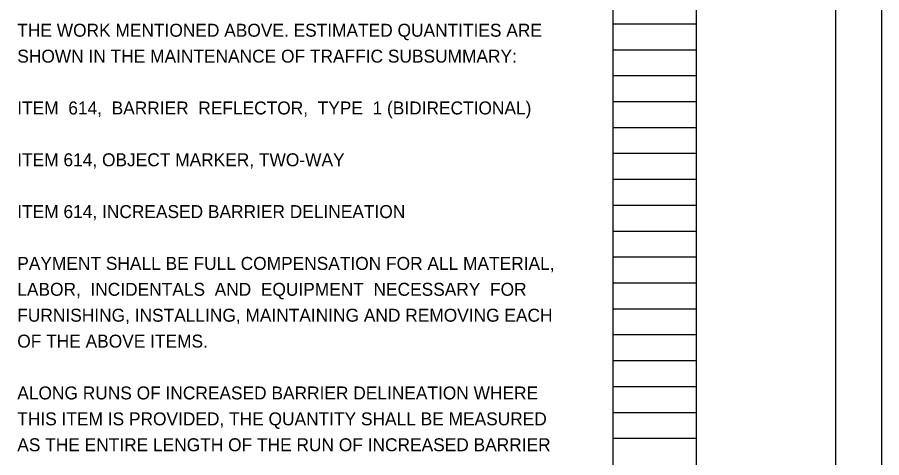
# Model space of a CAD drawing. Extents: x 0 to 34, y 0 to 22.
# Drawn here: x 24.66 to 34, y 4.69 to 9.45 of the extents above; entities that cross this region are included whole.
import ezdxf

# ---------------------------------------------------------------- set-up
doc = ezdxf.new("R2010")
doc.units = 0
for name, color, linetype in [('SH_Border', 7, 'Continuous'), ('SH_Cut_Line', 7, 'Continuous'), ('SH_Data', 7, 'Continuous'), ('SH_Text', 7, 'Continuous')]:
    doc.layers.add(name, color=color, linetype=linetype)

msp = doc.modelspace()

# ---------------------------------------------------------------- linework, layer by layer
at = {"layer": 'SH_Border'}
msp.add_line((32, 0.5), (32, 21.5), dxfattribs=at)
msp.add_lwpolyline([(1.5, 21.5), (33.5, 21.5), (33.5, 0.5), (1.5, 0.5)], close=True, dxfattribs=at)
at = {"layer": 'SH_Cut_Line'}
msp.add_lwpolyline([(0, 0), (34, 0), (34, 22), (0, 22)], close=True, dxfattribs=at)
at = {"layer": 'SH_Data'}
for p, q in [((31.1, 0.98), (31.1, 21.14)), ((32, 0.98), (32, 21.14)), ((31.1, 9.38), (32, 9.38)), ((31.1, 9.1), (32, 9.1)), ((31.1, 8.82), (32, 8.82)), ((31.1, 8.54), (32, 8.54)), ((31.1, 8.26), (32, 8.26)), ((31.1, 7.98), (32, 7.98)), ((31.1, 7.7), (32, 7.7)), ((31.1, 7.42), (32, 7.42)), ((31.1, 7.14), (32, 7.14)), ((31.1, 6.86), (32, 6.86)), ((31.1, 6.58), (32, 6.58)), ((31.1, 6.3), (32, 6.3)), ((31.1, 6.02), (32, 6.02)), ((31.1, 5.74), (32, 5.74)), ((31.1, 5.46), (32, 5.46)), ((31.1, 5.18), (32, 5.18)), ((31.1, 4.9), (32, 4.9))]:
    msp.add_line(p, q, dxfattribs=at)

# ---------------------------------------------------------------- texts
at = {"layer": 'SH_Text'}
for s, p in [('THE WORK MENTIONED ABOVE. ESTIMATED QUANTITIES ARE ', (24.66, 9.24)), ('SHOWN IN THE MAINTENANCE OF TRAFFIC SUBSUMMARY:', (24.66, 8.96)), ('ITEM  614,  BARRIER  REFLECTOR,  TYPE  1 (BIDIRECTIONAL) ', (24.66, 8.4)), ('ITEM 614, OBJECT MARKER, TWO-WAY ', (24.66, 7.84)), ('ITEM 614, INCREASED BARRIER DELINEATION ', (24.66, 7.28)), ('PAYMENT SHALL BE FULL COMPENSATION FOR ALL MATERIAL,', (24.66, 6.72)), ('LABOR,  INCIDENTALS  AND  EQUIPMENT  NECESSARY  FOR', (24.66, 6.44)), ('FURNISHING, INSTALLING, MAINTAINING AND REMOVING EACH', (24.66, 6.16)), ('OF THE ABOVE ITEMS.', (24.66, 5.88)), ('ALONG RUNS OF INCREASED BARRIER DELINEATION WHERE', (24.66, 5.32)), ('THIS ITEM IS PROVIDED, THE QUANTITY SHALL BE MEASURED', (24.66, 5.04)), ('AS THE ENTIRE LENGTH OF THE RUN OF INCREASED BARRIER', (24.66, 4.76))]:
    msp.add_text(s, height=0.14, dxfattribs=at).set_placement(p)

doc.saveas('drawing.dxf')
